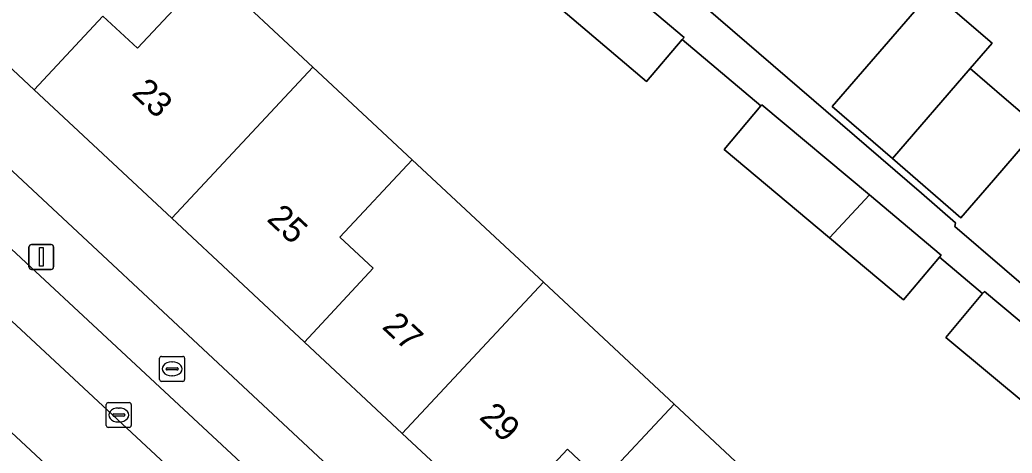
# Model space of a CAD drawing. Extents: x 162344 to 162869, y 381217 to 381818.
# Drawn here: x 162598.89 to 162638.72, y 381657.03 to 381674.43 of the extents above; entities that cross this region are included whole.
import ezdxf

# ---------------------------------------------------------------- set-up
doc = ezdxf.new("R2010")
doc.units = 0
for name, color, linetype in [('IMGEO_Brandkraan', 7, 'Continuous'), ('IMGEO_Erf', 7, 'Continuous'), ('IMGEO_Kolk', 7, 'Continuous'), ('IMGEO_Lichtmast', 7, 'Continuous'), ('IMGEO_Pand', 7, 'Continuous'), ('IMGEO_Pand_nummerreeks', 7, 'Continuous'), ('IMGEO_Parkeervlak_open', 7, 'Continuous'), ('IMGEO_Rijbaan_lokaal_open', 7, 'Continuous'), ('IMGEO_Voetpad_open', 7, 'Continuous')]:
    doc.layers.add(name, color=color, linetype=linetype)

msp = doc.modelspace()

# ---------------------------------------------------------------- linework, layer by layer
at = {"layer": 'IMGEO_Brandkraan'}
for p, q in [((162604.503, 381659.99), (162604.503, 381660.842)), ((162604.578, 381660.916), (162605.43, 381660.916)), ((162605.504, 381660.842), (162605.504, 381659.99)), ((162604.762, 381660.41), (162604.762, 381660.422)), ((162605.2, 381660.373), (162604.802, 381660.373)), ((162604.805, 381660.459), (162605.203, 381660.459)), ((162604.991, 381660.696), (162605.016, 381660.696)), ((162605.246, 381660.422), (162605.246, 381660.41)), ((162605.014, 381660.136), (162604.989, 381660.136)), ((162605.43, 381659.916), (162604.578, 381659.916))]:
    msp.add_line(p, q, dxfattribs=at)
for points in [[(162604.503, 381659.99), (162604.503, 381660.842)], [(162604.578, 381660.916), (162605.43, 381660.916)], [(162605.504, 381660.842), (162605.504, 381659.99)], [(162605.43, 381659.916), (162604.578, 381659.916)]]:
    msp.add_lwpolyline(points, dxfattribs=at)
for centre, radius, start, end in [((162604.58, 381660.84), 0.0765, 91.552, 178.448), ((162604.58, 381660.84), 0.0765, 91.552, 178.448), ((162605.428, 381660.84), 0.0765, 1.552, 88.448), ((162605.428, 381660.84), 0.0765, 1.552, 88.448), ((162604.802, 381660.419), 0.0403, 85.8775, 175.7526), ((162604.799, 381660.409), 0.0366, 178.938, 274.7102), ((162605.203, 381660.416), 0.043, 264.8664, 352.4533), ((162605.207, 381660.421), 0.0386, 1.7309, 96.639), ((162604.58, 381659.992), 0.0765, 181.552, 268.448), ((162604.58, 381659.992), 0.0765, 181.552, 268.448), ((162605.428, 381659.992), 0.0765, 271.552, 358.448), ((162605.428, 381659.992), 0.0765, 271.552, 358.448)]:
    msp.add_arc(centre, radius, start, end, dxfattribs=at)
for centre, major_axis, ratio, start_param, end_param in [((162604.99, 381660.416), (-0.387, 0.002), 0.722429, 4.712389, 7.853982), ((162605.015, 381660.416), (-0.39, 0.002), 0.717154, 1.570796, 4.712389)]:
    msp.add_ellipse(centre, major_axis=major_axis, ratio=ratio, start_param=start_param, end_param=end_param, dxfattribs=at)
at = {"layer": 'IMGEO_Erf'}
for points in [[(162564.247, 381700.434), (162622.51, 381646.029), (162633.056, 381636.194), (162637.13, 381640.474), (162638.739, 381642.093)], [(162615.01, 381684.77), (162635.091, 381667.467), (162636.457, 381666.288), (162636.428, 381666.14), (162640.413, 381662.701)], [(162606.512, 381676.399), (162610.649, 381672.537), (162614.637, 381668.816), (162619.721, 381664.07), (162619.909, 381663.895), (162625.154, 381659), (162629.04, 381655.373), (162632.905, 381651.766), (162634.538, 381650.242), (162638.193, 381646.83), (162632.53, 381640.762), (162628.583, 381644.446), (162623.376, 381649.305), (162618.106, 381654.224), (162614.245, 381657.827), (162610.315, 381661.495), (162604.986, 381666.469), (162599.464, 381671.623), (162595.782, 381675.059)], [(162639.487, 381658.819), (162636.064, 381661.68), (162637.535, 381663.439), (162635.802, 381664.902), (162634.365, 381663.187), (162631.389, 381665.68), (162627.165, 381669.221), (162628.634, 381670.974), (162625.482, 381673.644), (162624.051, 381671.956), (162620.432, 381675.025)]]:
    msp.add_lwpolyline(points, dxfattribs=at)
msp.add_lwpolyline([(162637.043, 381672.476), (162638.402, 381671.303), (162639.79, 381670.105), (162637.974, 381668.001), (162636.665, 381666.484), (162633.916, 381668.861), (162631.497, 381670.953), (162635.505, 381675.587), (162637.924, 381673.494)], close=True, dxfattribs=at)
at = {"layer": 'IMGEO_Kolk'}
for p, q in [((162602.361, 381658.138), (162602.361, 381658.99)), ((162602.436, 381659.064), (162603.288, 381659.064)), ((162602.849, 381658.844), (162602.874, 381658.844)), ((162603.362, 381658.99), (162603.362, 381658.138)), ((162602.62, 381658.558), (162602.62, 381658.57)), ((162603.058, 381658.521), (162602.66, 381658.521)), ((162602.663, 381658.607), (162603.061, 381658.607)), ((162603.104, 381658.57), (162603.104, 381658.558)), ((162603.288, 381658.064), (162602.436, 381658.064)), ((162602.872, 381658.284), (162602.847, 381658.284))]:
    msp.add_line(p, q, dxfattribs=at)
for points in [[(162602.361, 381658.138), (162602.361, 381658.99)], [(162602.436, 381659.064), (162603.288, 381659.064)], [(162603.362, 381658.99), (162603.362, 381658.138)], [(162603.288, 381658.064), (162602.436, 381658.064)]]:
    msp.add_lwpolyline(points, dxfattribs=at)
for centre, radius, start, end in [((162602.438, 381658.988), 0.0765, 91.552, 178.448), ((162602.438, 381658.988), 0.0765, 91.552, 178.448), ((162603.286, 381658.988), 0.0765, 1.552, 88.448), ((162603.286, 381658.988), 0.0765, 1.552, 88.448), ((162602.66, 381658.567), 0.0403, 85.8775, 175.7526), ((162602.657, 381658.557), 0.0366, 178.938, 274.7102), ((162603.061, 381658.564), 0.043, 264.8664, 352.4533), ((162603.065, 381658.569), 0.0386, 1.7309, 96.639), ((162602.438, 381658.14), 0.0765, 181.552, 268.448), ((162602.438, 381658.14), 0.0765, 181.552, 268.448), ((162603.286, 381658.14), 0.0765, 271.552, 358.448), ((162603.286, 381658.14), 0.0765, 271.552, 358.448)]:
    msp.add_arc(centre, radius, start, end, dxfattribs=at)
for centre, major_axis, ratio, start_param, end_param in [((162602.848, 381658.564), (-0.387, 0.002), 0.722429, 4.712389, 7.853982), ((162602.873, 381658.564), (-0.39, 0.002), 0.717154, 1.570796, 4.712389)]:
    msp.add_ellipse(centre, major_axis=major_axis, ratio=ratio, start_param=start_param, end_param=end_param, dxfattribs=at)
at = {"layer": 'IMGEO_Lichtmast'}
for p, q in [((162599.259, 381664.511), (162599.259, 381665.311)), ((162599.259, 381665.311), (162599.259, 381664.511)), ((162599.359, 381665.411), (162600.149, 381665.411)), ((162600.149, 381665.411), (162599.359, 381665.411)), ((162600.249, 381665.311), (162600.249, 381664.511)), ((162600.249, 381664.511), (162600.249, 381665.311)), ((162600.149, 381664.411), (162599.359, 381664.411)), ((162599.359, 381664.411), (162600.149, 381664.411))]:
    msp.add_line(p, q, dxfattribs=at)
msp.add_lwpolyline([(162599.679, 381665.286), (162599.829, 381665.286), (162599.829, 381664.536), (162599.679, 381664.536), (162599.679, 381665.286)], dxfattribs=at)
for centre, start, end in [((162599.359, 381665.311), 90, 180), ((162599.359, 381665.311), 90, 180), ((162600.149, 381665.311), 0, 90), ((162600.149, 381665.311), 360, 90), ((162599.359, 381664.511), 180, 270), ((162599.359, 381664.511), 180, 270), ((162600.149, 381664.511), 270, 0), ((162600.149, 381664.511), 270, 0)]:
    msp.add_arc(centre, 0.1, start, end, dxfattribs=at)
at = {"layer": 'IMGEO_Pand'}
for points in [[(162606.512, 381676.399), (162601.445, 381681.127), (162595.782, 381675.059), (162599.464, 381671.623), (162602.229, 381674.586), (162603.614, 381673.294)], [(162622.019, 381676.725), (162620.432, 381675.025), (162624.051, 381671.956), (162625.482, 381673.644), (162625.554, 381673.728)], [(162606.512, 381676.399), (162603.614, 381673.294), (162602.229, 381674.586), (162599.464, 381671.623), (162604.986, 381666.469), (162610.649, 381672.537)], [(162637.043, 381672.476), (162637.924, 381673.494), (162635.505, 381675.587), (162631.497, 381670.953), (162633.916, 381668.861)], [(162610.649, 381672.537), (162604.986, 381666.469), (162610.315, 381661.495), (162613.08, 381664.458), (162611.738, 381665.71), (162614.637, 381668.816)], [(162639.79, 381670.105), (162638.402, 381671.303), (162637.043, 381672.476), (162633.916, 381668.861), (162636.665, 381666.484), (162637.974, 381668.001)], [(162628.634, 381670.974), (162627.165, 381669.221), (162631.389, 381665.68), (162632.995, 381667.401), (162628.674, 381671.022)], [(162619.909, 381663.895), (162619.721, 381664.07), (162614.637, 381668.816), (162611.738, 381665.71), (162613.08, 381664.458), (162610.315, 381661.495), (162614.245, 381657.827)], [(162632.995, 381667.401), (162631.389, 381665.68), (162634.365, 381663.187), (162635.802, 381664.902), (162635.874, 381664.988)], [(162619.909, 381663.895), (162614.245, 381657.827), (162618.106, 381654.224), (162620.871, 381657.187), (162622.256, 381655.895), (162625.154, 381659)], [(162637.535, 381663.439), (162636.064, 381661.68), (162639.487, 381658.819), (162641.133, 381660.582), (162637.609, 381663.528)], [(162629.04, 381655.373), (162625.154, 381659), (162622.256, 381655.895), (162620.871, 381657.187), (162618.106, 381654.224), (162623.376, 381649.305)]]:
    msp.add_lwpolyline(points, close=True, dxfattribs=at)
at = {"layer": 'IMGEO_Parkeervlak_open'}
for points in [[(162542.273, 381714.77), (162580.185, 381679.418), (162591.19, 381669.184), (162593.726, 381666.826), (162618.042, 381644.213), (162632.252, 381630.976)], [(162631.144, 381634.866), (162631.092, 381634.929), (162619.498, 381645.735), (162581.635, 381680.986)]]:
    msp.add_lwpolyline(points, dxfattribs=at)
at = {"layer": 'IMGEO_Rijbaan_lokaal_open'}
msp.add_lwpolyline([(162593.726, 381666.826), (162591.536, 381664.4), (162600.499, 381656.056), (162611.825, 381645.502), (162617.846, 381639.9), (162621.502, 381636.51), (162624.566, 381633.613), (162626.089, 381632.217), (162633.2, 381625.535), (162635.145, 381623.708), (162636.238, 381622.763), (162638.503, 381625.198), (162637.522, 381626.077), (162632.252, 381630.976), (162618.042, 381644.213)], close=True, dxfattribs=at)
at = {"layer": 'IMGEO_Voetpad_open'}
for points in [[(162546.116, 381714.053), (162581.635, 381680.986), (162619.498, 381645.735), (162631.092, 381634.929), (162631.144, 381634.866), (162633.394, 381635.882), (162633.056, 381636.194), (162622.51, 381646.029), (162564.247, 381700.434), (162563.297, 381701.321), (162542.992, 381720.281), (162544.927, 381722.323), (162550.499, 381728.32), (162549.382, 381729.332), (162549.177, 381729.094), (162542.325, 381735.015), (162542.783, 381735.545), (162540.53, 381737.492), (162538.277, 381739.439), (162536.025, 381741.385), (162533.772, 381743.332), (162531.519, 381745.279), (162527.407, 381740.337), (162535.988, 381732.91)], [(162626.089, 381632.217), (162624.566, 381633.613), (162621.502, 381636.51), (162620.666, 381635.608), (162617.099, 381639.112), (162617.846, 381639.9), (162611.825, 381645.502), (162600.499, 381656.056), (162591.536, 381664.4), (162588.969, 381666.789), (162586.238, 381669.332), (162574.275, 381680.474), (162573.453, 381681.241), (162560.818, 381693.021), (162548.027, 381704.879), (162546.399, 381706.372)], [(162640.413, 381662.701), (162636.428, 381666.14), (162636.457, 381666.288), (162635.091, 381667.467), (162615.01, 381684.77)], [(162622.019, 381676.725), (162625.554, 381673.728), (162625.482, 381673.644), (162628.634, 381670.974), (162628.674, 381671.022), (162632.995, 381667.401), (162635.874, 381664.988), (162635.802, 381664.902), (162637.535, 381663.439), (162637.609, 381663.528), (162641.133, 381660.582)]]:
    msp.add_lwpolyline(points, dxfattribs=at)

# ---------------------------------------------------------------- texts
at = {"layer": 'IMGEO_Pand_nummerreeks'}
for s, rotation, p in [('23', 316.9758, (162603.341, 381671.452)), ('25', 316.9758, (162608.766, 381666.388)), ('27', 316.9766, (162613.396, 381662.067)), ('29', 316.9766, (162617.291, 381658.432))]:
    msp.add_text(s, height=1, rotation=rotation, dxfattribs=at).set_placement(p)

doc.saveas('drawing.dxf')
